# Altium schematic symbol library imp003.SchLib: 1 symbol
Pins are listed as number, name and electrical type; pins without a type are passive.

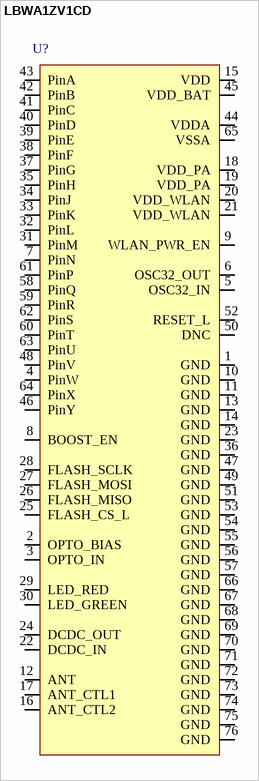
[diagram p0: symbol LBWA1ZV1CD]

## LBWA1ZV1CD
designator U?, comment Murata Imp Module  (value not drawn)
pins: 1 GND, 2 OPTO_BIAS, 3 OPTO_IN, 4 PinW, 5 OSC32_IN, 6 OSC32_OUT, 7 PinN, 8 BOOST_EN, 9 WLAN_PWR_EN, 10 GND, 11 GND, 12 ANT, 13 GND, 14 GND, 15 VDD, 16 ANT_CTL2, 17 ANT_CTL1, 18 VDD_PA, 19 VDD_PA, 20 VDD_WLAN, 21 VDD_WLAN, 22 DCDC_IN, 23 GND, 24 DCDC_OUT, 25 FLASH_CS_L, 26 FLASH_MISO, 27 FLASH_MOSI, 28 FLASH_SCLK, 29 LED_RED, 30 LED_GREEN, 31 PinM, 32 PinL, 33 PinK, 34 PinJ, 35 PinH, 36 GND, 37 PinG, 38 PinF, 39 PinE, 40 PinD, 41 PinC, 42 PinB, 43 PinA, 44 VDDA, 45 VDD_BAT, 46 PinY, 47 GND, 48 PinV, 49 GND, 50 DNC, 51 GND, 52 RESET_L, 53 GND, 54 GND, 55 GND, 56 GND, 57 GND, 58 PinQ, 59 PinR, 60 PinT, 61 PinP, 62 PinS, 63 PinU, 64 PinX, 65 VSSA, 66 GND, 67 GND, 68 GND, 69 GND, 70 GND, 71 GND, 72 GND, 73 GND, 74 GND, 75 GND, 76 GND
